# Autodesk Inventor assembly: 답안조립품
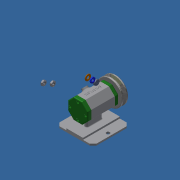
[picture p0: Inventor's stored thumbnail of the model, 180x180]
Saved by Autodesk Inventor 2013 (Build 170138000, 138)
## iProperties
Created: 2018-06
Part Number: 답안조립품
Document SubType Name: Assembly
Designer: Administrator
Author: Administrator
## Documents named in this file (15)
- C:\Users\Administrator\Desktop\480607V1007\답안조립품.iam
- C:\Users\Administrator\Desktop\480607V1007\본체.ipt
- C:\Users\Administrator\Desktop\480607V1007\베어링 15x32x9.ipt
- C:\Users\Administrator\Desktop\480607V1007\뒤커버.ipt
- C:\Users\Administrator\Desktop\480607V1007\앞커버.ipt
- C:\Users\Administrator\Desktop\480607V1007\오일 실 15 25 7.ipt
- C:\Users\Administrator\Desktop\480607V1007\V벨트풀리.ipt
- C:\Users\Administrator\Desktop\480607V1007\고무캡.ipt
- C:\Users\Administrator\Desktop\480607V1007\스프링와셔 8.ipt
- C:\Users\Administrator\Desktop\480607V1007\와셔 8x17.ipt
- C:\Users\Administrator\Desktop\480607V1007\축.ipt
- C:\Users\Administrator\Desktop\480607V1007\키 3x3x12.ipt
- 키 3x3x12.ipt
- C:\Users\Administrator\Desktop\480607V1007\너트 M8.ipt
- 너트 M8.ipt
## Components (2 placed, 2 different names)
1. V벨트풀리:1
2. 고무캡:1
